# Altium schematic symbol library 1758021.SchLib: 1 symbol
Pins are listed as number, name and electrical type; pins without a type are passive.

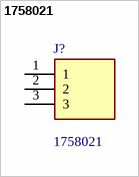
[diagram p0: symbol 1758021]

## 1758021
designator J?
PCB header, nominal cross section: 2.5 mm?, color: green, nominal current: 12 A, rated voltage (III/2): 320 V, contact surface: Tin, type of contact: Male connector, Number of potentials: 3, Number of rows: 1, Number of positions per row: 3, number of connections: 3, product range: MSTBV 2,5/..-G, pitch: 5.08 mm, mounting: Wave soldering, pin layout: Linear pinning, solder pin [P]: 3.9 mm, Stecksystem: CLASSIC COMBICON, Locking: without, type of packaging: packed in cardboard; Manufacturer_Name: Phoenix Contact; Geometry.Height: 12.15mm
footprint 1758021
pins: 1, 2, 3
